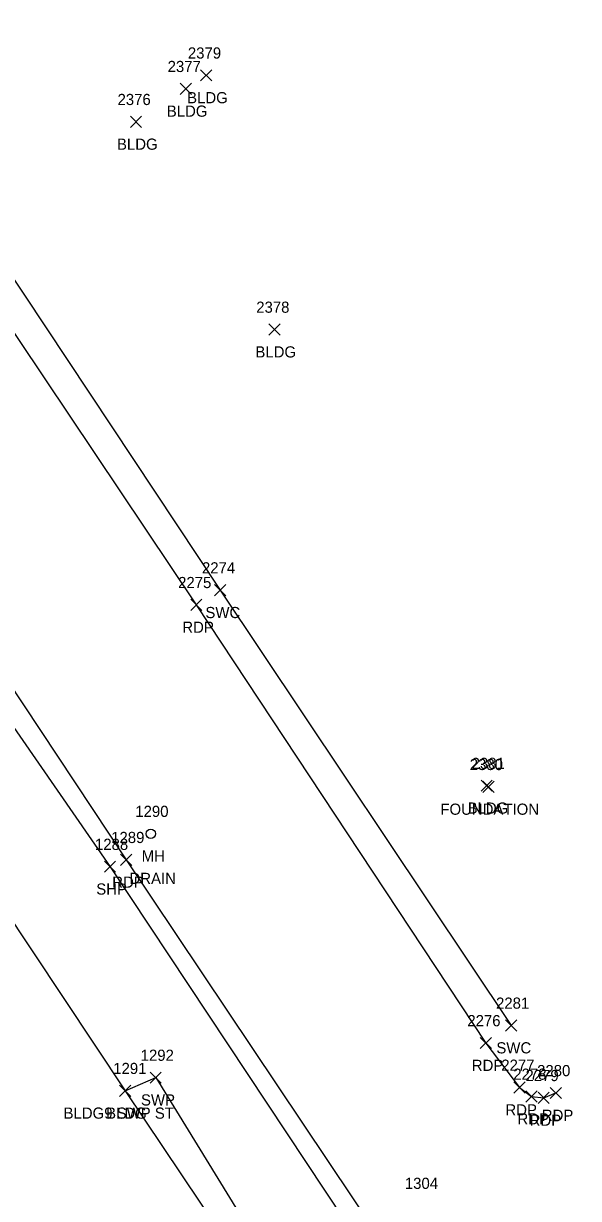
# Model space of a CAD drawing. Extents: x 1635588 to 1637550, y 621583 to 623638.
# Drawn here: x 1636794.5 to 1636894, y 622475 to 622685.3 of the extents above; entities that cross this region are included whole.
import ezdxf

# ---------------------------------------------------------------- set-up
doc = ezdxf.new("R2010")
doc.units = 0
for name, color, linetype in [('L_A', 7, 'Continuous'), ('L_I', 7, 'Continuous'), ('L_TIC', 7, 'Continuous'), ('LBC', 7, 'Continuous'), ('P_A', 7, 'Continuous'), ('P_I', 7, 'Continuous'), ('P_TIC', 7, 'Continuous'), ('PET', 7, 'Continuous'), ('PSP', 7, 'Continuous'), ('R_A', 7, 'Continuous'), ('R_I', 7, 'Continuous'), ('R_TIC', 7, 'Continuous'), ('RSW', 7, 'Continuous'), ('U_A', 7, 'Continuous'), ('U_C', 7, 'Continuous'), ('U_I', 7, 'Continuous'), ('UUMH', 7, 'Continuous')]:
    doc.layers.add(name, color=color, linetype=linetype)

msp = doc.modelspace()

# ---------------------------------------------------------------- linework, layer by layer
at = {"layer": 'L_TIC'}
for points in [[(1636826.26, 622675.06), (1636828.26, 622677.06)], [(1636828.26, 622675.06), (1636826.26, 622677.06)], [(1636822.62, 622672.65), (1636824.62, 622674.65)], [(1636824.62, 622672.65), (1636822.62, 622674.65)], [(1636813.7, 622666.74), (1636815.7, 622668.74)], [(1636815.7, 622666.74), (1636813.7, 622668.74)], [(1636838.49, 622629.55), (1636840.49, 622631.55)], [(1636840.49, 622629.55), (1636838.49, 622631.55)], [(1636876.5, 622547.88), (1636878.5, 622549.88)], [(1636878.5, 622547.88), (1636876.5, 622549.88)], [(1636876.82, 622547.68), (1636878.82, 622549.68)], [(1636878.82, 622547.68), (1636876.82, 622549.68)], [(1636811.75, 622493.27), (1636813.75, 622495.27)], [(1636813.75, 622493.27), (1636811.75, 622495.27)]]:
    msp.add_lwpolyline(points, dxfattribs=at)
at = {"layer": 'LBC'}
msp.add_lwpolyline([(1636762.84, 622569.3), (1636812.75, 622494.27), (1636839.75, 622454.02), (1636807.39, 622432.4)], dxfattribs=at)
at = {"layer": 'P_TIC'}
for points in [[(1636824.5, 622580.26), (1636826.5, 622582.26)], [(1636826.5, 622580.26), (1636824.5, 622582.26)], [(1636811.95, 622534.62), (1636813.95, 622536.62)], [(1636813.95, 622534.62), (1636811.95, 622536.62)], [(1636809.04, 622533.39), (1636811.04, 622535.39)], [(1636811.04, 622533.39), (1636809.04, 622535.39)], [(1636876.35, 622501.82), (1636878.35, 622503.82)], [(1636878.35, 622501.82), (1636876.35, 622503.82)], [(1636882.38, 622493.85), (1636884.38, 622495.85)], [(1636884.38, 622493.85), (1636882.38, 622495.85)], [(1636884.53, 622492.24), (1636886.53, 622494.24)], [(1636886.53, 622492.24), (1636884.53, 622494.24)], [(1636886.72, 622492), (1636888.72, 622494)], [(1636888.72, 622492), (1636886.72, 622494)], [(1636888.89, 622492.88), (1636890.89, 622494.88)], [(1636890.89, 622492.88), (1636888.89, 622494.88)]]:
    msp.add_lwpolyline(points, dxfattribs=at)
at = {"layer": 'PET'}
for points in [[(1636496.54, 623045.3), (1636533.69, 622970.65), (1636546.95, 622944.69), (1636557.06, 622926.23), (1636579, 622887.89), (1636603.72, 622849.48), (1636616.07, 622830.82), (1636647.79, 622783.76), (1636703.25, 622700.68), (1636737.08, 622649.81), (1636763.83, 622609.67), (1636812.95, 622535.62), (1636858.06, 622468.21), (1636878.24, 622438.26), (1636911.18, 622389.38), (1636974.88, 622293.33), (1636986.61, 622276.7), (1637016.63, 622231.99)], [(1636784.1, 622675.92), (1636777.21, 622670.99), (1636775.52, 622667.99), (1636774.5, 622663.78), (1636774.23, 622660.96), (1636776.27, 622655.22), (1636780.06, 622648.99), (1636825.5, 622581.26), (1636877.35, 622502.82), (1636883.38, 622494.85), (1636885.53, 622493.24), (1636887.72, 622493), (1636889.89, 622493.88)]]:
    msp.add_lwpolyline(points, dxfattribs=at)
at = {"layer": 'PSP'}
msp.add_lwpolyline([(1636412.61, 623220.07), (1636436.6, 623167.3), (1636456.23, 623125.07), (1636460.67, 623115.98), (1636475.52, 623084.87), (1636494.51, 623045.42), (1636524.16, 622986.51), (1636530.74, 622972.24), (1636554.07, 622925.3), (1636577.18, 622886.3), (1636601.72, 622847.41), (1636613.46, 622830.09), (1636645.38, 622782.47), (1636700.61, 622698.86), (1636734.28, 622648.07), (1636752.12, 622619.3), (1636752.46, 622616.81), (1636755.34, 622613.42), (1636810.04, 622534.39), (1636855.63, 622465.66), (1636874.76, 622437.49), (1636904.15, 622393.55)], dxfattribs=at)
at = {"layer": 'R_TIC'}
for points in [[(1636828.77, 622582.89), (1636830.77, 622584.89)], [(1636830.77, 622582.89), (1636828.77, 622584.89)], [(1636880.88, 622504.96), (1636882.88, 622506.96)], [(1636882.88, 622504.96), (1636880.88, 622506.96)], [(1636817.23, 622495.63), (1636819.23, 622497.63)], [(1636819.23, 622495.63), (1636817.23, 622497.63)], [(1636811.75, 622493.27), (1636813.75, 622495.27)], [(1636813.75, 622493.27), (1636811.75, 622495.27)]]:
    msp.add_lwpolyline(points, dxfattribs=at)
at = {"layer": 'RSW'}
for points in [[(1636787.39, 622671.39), (1636782.02, 622667.01), (1636780.03, 622665.03), (1636779.97, 622662.41), (1636781.07, 622657.75), (1636781.38, 622656.72), (1636782.93, 622654.45), (1636829.77, 622583.89), (1636881.88, 622505.96)], [(1636812.75, 622494.27), (1636818.23, 622496.63), (1636840.44, 622460.49), (1636841.84, 622458.22), (1636845.78, 622454.85)]]:
    msp.add_lwpolyline(points, dxfattribs=at)
at = {"layer": 'UUMH'}
for p, q in [((1636817.34, 622540.29), (1636817.34, 622540.29)), ((1636818.18, 622540.29), (1636818.18, 622540.29))]:
    msp.add_line(p, q, dxfattribs=at)
msp.add_circle((1636817.34, 622540.29), 0.833, dxfattribs=at)

# ---------------------------------------------------------------- texts
at = {"layer": 'L_A'}
for s, p in [('BLDG', (1636823.85, 622671.06)), ('BLDG', (1636820.21, 622668.65)), ('BLDG', (1636811.29, 622662.74)), ('BLDG', (1636836.08, 622625.55)), ('FOUNDATION', (1636869.21, 622543.68)), ('BLDG', (1636874.09, 622543.88)), ('BLDG', (1636809.34, 622489.27))]:
    msp.add_text(s, height=2, dxfattribs=at).set_placement(p)
at = {"layer": 'L_I'}
for s, p in [('2379', (1636823.99, 622679.06)), ('2377', (1636820.36, 622676.65)), ('2376', (1636811.39, 622670.74)), ('2378', (1636836.23, 622633.55)), ('2380', (1636874.47, 622551.68)), ('2381', (1636874.81, 622551.88)), ('1291', (1636810.62, 622497.27))]:
    msp.add_text(s, height=2, dxfattribs=at).set_placement(p)
at = {"layer": 'P_A'}
for s, p in [('RDP', (1636822.99, 622576.26)), ('RDP', (1636810.44, 622530.62)), ('SHP', (1636807.58, 622529.39)), ('RDP', (1636874.84, 622497.82)), ('RDP', (1636880.86, 622489.85)), ('RDP', (1636883.02, 622488.24)), ('RDP', (1636885.21, 622488)), ('RDP', (1636887.38, 622488.88))]:
    msp.add_text(s, height=2, dxfattribs=at).set_placement(p)
at = {"layer": 'P_I'}
for s, p in [('2275', (1636822.24, 622584.26)), ('1289', (1636810.25, 622538.62)), ('1288', (1636807.35, 622537.39)), ('2276', (1636874.04, 622505.82)), ('2277', (1636880.12, 622497.85)), ('2278', (1636882.27, 622496.24)), ('2279', (1636884.45, 622496)), ('2280', (1636886.54, 622496.88))]:
    msp.add_text(s, height=2, dxfattribs=at).set_placement(p)
at = {"layer": 'R_A'}
for s, p in [('SWC', (1636827.13, 622578.89)), ('SWC', (1636879.24, 622500.96)), ('SWP', (1636815.59, 622491.63)), ('BLDG9 SWP ST', (1636801.72, 622489.27))]:
    msp.add_text(s, height=2, dxfattribs=at).set_placement(p)
at = {"layer": 'R_I'}
for s, p in [('2274', (1636826.51, 622586.89)), ('2281', (1636879.18, 622508.96)), ('1292', (1636815.53, 622499.63)), ('1291', (1636810.62, 622497.27))]:
    msp.add_text(s, height=2, dxfattribs=at).set_placement(p)
at = {"layer": 'U_A'}
msp.add_text('MH', height=2, dxfattribs=at).set_placement((1636815.71, 622535.29))
at = {"layer": 'U_C'}
msp.add_text('DRAIN', height=2, dxfattribs=at).set_placement((1636813.53, 622531.29))
at = {"layer": 'U_I'}
for s, p in [('1290', (1636814.57, 622543.29)), ('1304', (1636862.85, 622476.7))]:
    msp.add_text(s, height=2, dxfattribs=at).set_placement(p)

doc.saveas('drawing.dxf')
